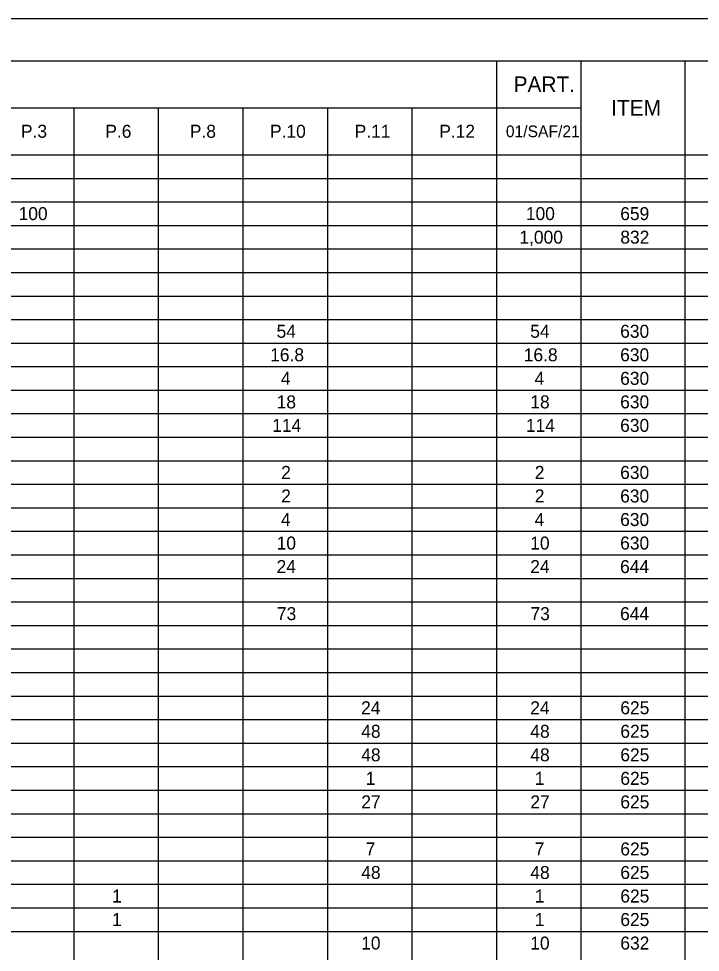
# Model space of a CAD drawing. Extents: x 0 to 34, y 0 to 22.
# Drawn here: x 8.89 to 16.99, y 10.89 to 22 of the extents above; entities that cross this region are included whole.
import ezdxf

# ---------------------------------------------------------------- set-up
doc = ezdxf.new("R2010")
doc.units = 0
for name, color, linetype in [('SH_Border', 7, 'Continuous'), ('SH_Cut_Line', 7, 'Continuous'), ('SH_Text', 7, 'Continuous')]:
    doc.layers.add(name, color=color, linetype=linetype)

msp = doc.modelspace()

# ---------------------------------------------------------------- linework, layer by layer
at = {"layer": 'SH_Border'}
msp.add_lwpolyline([(1.5, 21.5), (33.5, 21.5), (33.5, 0.5), (1.5, 0.5)], close=True, dxfattribs=at)
at = {"layer": 'SH_Cut_Line'}
msp.add_lwpolyline([(0, 0), (34, 0), (34, 22), (0, 22)], close=True, dxfattribs=at)
at = {"layer": 'SH_Text'}
for p, q in [((1.5, 21.5), (32, 21.5)), ((14.567, 21.5), (14.567, 0.5)), ((15.572, 21.5), (15.572, 0.5)), ((16.808, 21.5), (16.808, 0.5)), ((1.5, 20.94), (15.572, 20.94)), ((9.541, 20.94), (9.541, 0.5)), ((10.546, 20.94), (10.546, 0.5)), ((11.551, 20.94), (11.551, 0.5)), ((12.557, 20.94), (12.557, 0.5)), ((13.562, 20.94), (13.562, 0.5)), ((1.5, 20.38), (32, 20.38)), ((1.5, 20.1), (32, 20.1)), ((1.5, 19.82), (32, 19.82)), ((1.5, 19.54), (32, 19.54)), ((1.5, 19.26), (32, 19.26)), ((1.5, 18.98), (32, 18.98)), ((1.5, 18.7), (32, 18.7)), ((1.5, 18.42), (32, 18.42)), ((1.5, 18.14), (32, 18.14)), ((1.5, 17.86), (32, 17.86)), ((1.5, 17.58), (32, 17.58)), ((1.5, 17.3), (32, 17.3)), ((1.5, 17.02), (32, 17.02)), ((1.5, 16.74), (32, 16.74)), ((1.5, 16.46), (32, 16.46)), ((1.5, 16.18), (32, 16.18)), ((1.5, 15.9), (32, 15.9)), ((1.5, 15.62), (32, 15.62)), ((1.5, 15.34), (32, 15.34)), ((1.5, 15.06), (32, 15.06)), ((1.5, 14.78), (32, 14.78)), ((1.5, 14.5), (32, 14.5)), ((1.5, 14.22), (32, 14.22)), ((1.5, 13.94), (32, 13.94)), ((1.5, 13.66), (32, 13.66)), ((1.5, 13.38), (32, 13.38)), ((1.5, 13.1), (32, 13.1)), ((1.5, 12.82), (32, 12.82)), ((1.5, 12.54), (32, 12.54)), ((1.5, 12.26), (32, 12.26)), ((1.5, 11.98), (32, 11.98)), ((1.5, 11.7), (32, 11.7)), ((1.5, 11.42), (32, 11.42)), ((1.5, 11.14), (32, 11.14))]:
    msp.add_line(p, q, dxfattribs=at)

# ---------------------------------------------------------------- texts
for s, height, p in [('PART.', 0.1855, (14.771, 21.127)), ('ITEM', 0.1855, (15.931, 20.847)), ('P.3', 0.1546, (8.914, 20.583)), ('P.6', 0.1546, (9.917, 20.583)), ('P.8', 0.1546, (10.922, 20.583)), ('P.10', 0.1546, (11.875, 20.583)), ('P.11', 0.1546, (12.882, 20.583)), ('P.12', 0.1546, (13.887, 20.583)), ('01/SAF/21', 0.1391, (14.679, 20.59)), ('100', 0.1546, (8.886, 19.603)), ('100', 0.1546, (14.917, 19.603)), ('659', 0.1546, (16.039, 19.603)), ('1,000', 0.1546, (14.84, 19.323)), ('832', 0.1546, (16.04, 19.323)), ('54', 0.1546, (11.953, 18.203)), ('54', 0.1546, (14.969, 18.203)), ('630', 0.1546, (16.038, 18.203)), ('16.8', 0.1546, (11.877, 17.923)), ('16.8', 0.1546, (14.892, 17.923)), ('630', 0.1546, (16.038, 17.923)), ('4', 0.155, (12.005, 17.643)), ('4', 0.155, (15.021, 17.643)), ('630', 0.1546, (16.038, 17.643)), ('18', 0.1546, (11.954, 17.363)), ('18', 0.1546, (14.97, 17.363)), ('630', 0.1546, (16.038, 17.363)), ('114', 0.1546, (11.901, 17.083)), ('114', 0.1546, (14.917, 17.083)), ('630', 0.1546, (16.038, 17.083)), ('2', 0.155, (12.008, 16.523)), ('2', 0.155, (15.023, 16.523)), ('630', 0.1546, (16.038, 16.523)), ('2', 0.155, (12.008, 16.243)), ('2', 0.155, (15.023, 16.243)), ('630', 0.1546, (16.038, 16.243)), ('4', 0.155, (12.005, 15.963)), ('4', 0.155, (15.021, 15.963)), ('630', 0.1546, (16.038, 15.963)), ('10', 0.1546, (11.954, 15.683)), ('10', 0.1546, (14.969, 15.683)), ('630', 0.1546, (16.038, 15.683)), ('24', 0.1546, (11.953, 15.403)), ('24', 0.1546, (14.969, 15.403)), ('644', 0.1546, (16.037, 15.403)), ('73', 0.1546, (11.957, 14.843)), ('73', 0.1546, (14.972, 14.843)), ('644', 0.1546, (16.037, 14.843)), ('24', 0.1546, (12.958, 13.723)), ('24', 0.1546, (14.969, 13.723)), ('625', 0.1546, (16.04, 13.723)), ('48', 0.1546, (12.96, 13.443)), ('48', 0.1546, (14.97, 13.443)), ('625', 0.1546, (16.04, 13.443)), ('48', 0.1546, (12.96, 13.163)), ('48', 0.1546, (14.97, 13.163)), ('625', 0.1546, (16.04, 13.163)), ('1', 0.155, (13.013, 12.883)), ('1', 0.155, (15.023, 12.883)), ('625', 0.1546, (16.04, 12.883)), ('27', 0.1546, (12.96, 12.603)), ('27', 0.1546, (14.97, 12.603)), ('625', 0.1546, (16.04, 12.603)), ('7', 0.155, (13.012, 12.043)), ('7', 0.155, (15.022, 12.043)), ('625', 0.1546, (16.04, 12.043)), ('48', 0.1546, (12.96, 11.763)), ('48', 0.1546, (14.97, 11.763)), ('625', 0.1546, (16.04, 11.763)), ('1', 0.155, (9.997, 11.483)), ('1', 0.155, (15.023, 11.483)), ('625', 0.1546, (16.04, 11.483)), ('1', 0.155, (9.997, 11.203)), ('1', 0.155, (15.023, 11.203)), ('625', 0.1546, (16.04, 11.203)), ('10', 0.1546, (12.959, 10.923)), ('10', 0.1546, (14.969, 10.923)), ('632', 0.1546, (16.04, 10.923))]:
    msp.add_text(s, height=height, dxfattribs=at).set_placement(p)

doc.saveas('drawing.dxf')
